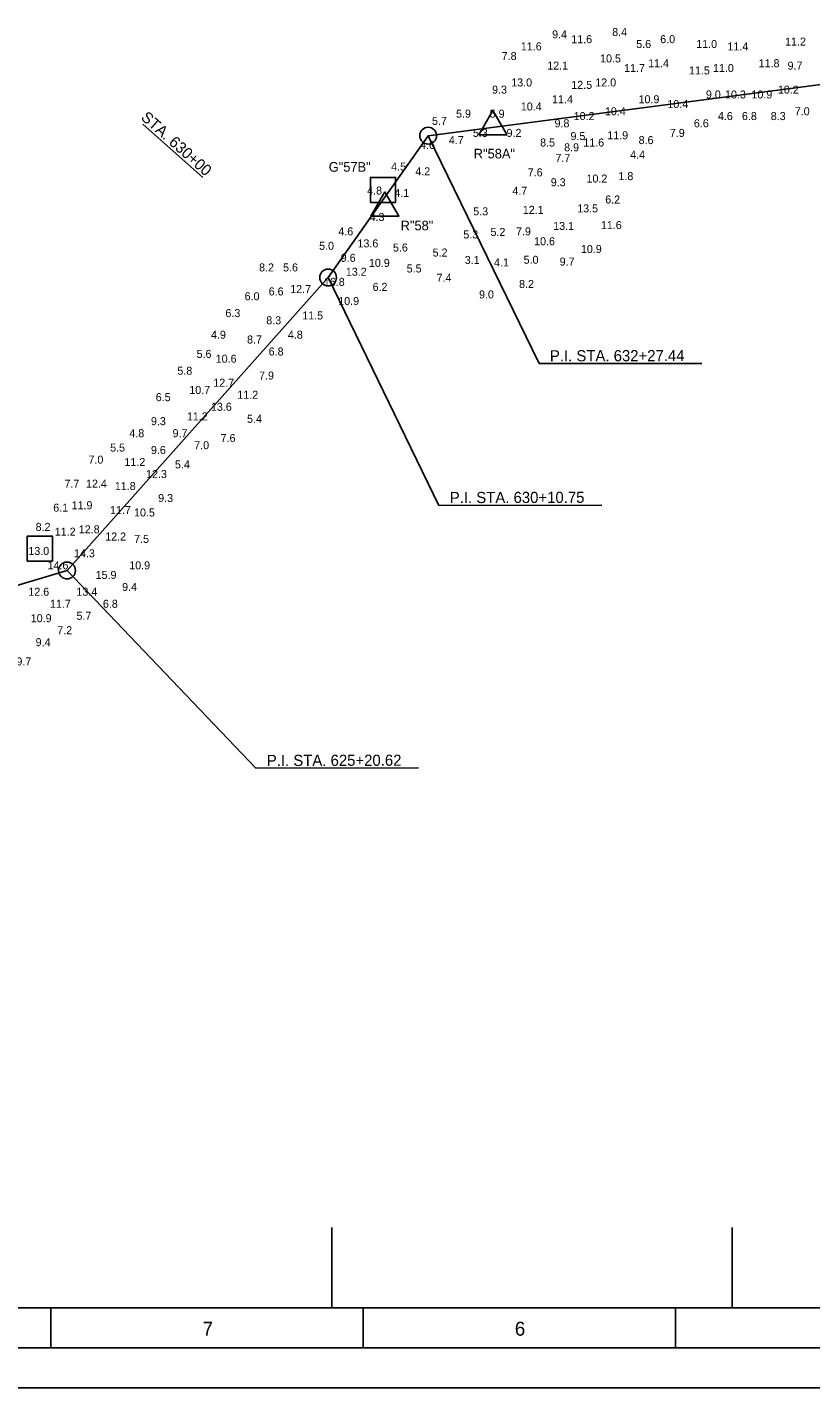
# Model space of a CAD drawing. Extents: x 442804 to 447204, y 1614037 to 1617437.
# Drawn here: x 444120 to 445098, y 1614037 to 1615736 of the extents above; entities that cross this region are included whole.
import ezdxf

# ---------------------------------------------------------------- set-up
doc = ezdxf.new("R2010")
doc.units = 0
for name, color, linetype in [('Default', 7, 'Continuous'), ('G-ANNO-NPLT', 7, 'Continuous'), ('G-ANNO-TTLB', 7, 'Continuous'), ('V-ALGN-TEXT', 7, 'Continuous'), ('V-CHAN-CNTR', 7, 'Continuous'), ('V-CHAN-CNTR-IDEN', 7, 'Continuous'), ('V-CHAN-NAID', 7, 'Continuous'), ('V-TOPO-COOR-STAT', 7, 'Continuous'), ('V-TOPO-SOUN', 7, 'Continuous')]:
    doc.layers.add(name, color=color, linetype=linetype)

msp = doc.modelspace()

# ---------------------------------------------------------------- linework, layer by layer
at = {"layer": 'G-ANNO-NPLT'}
msp.add_lwpolyline([(442804.3, 1617437.2), (447204.3, 1617437.2), (447204.3, 1614037.3), (442804.3, 1614037.3)], close=True, dxfattribs=at)
at = {"layer": 'G-ANNO-TTLB'}
for p, q in [((444149.3, 1614087.3), (444149.3, 1614137.3)), ((444539.3, 1614087.3), (444539.3, 1614137.3)), ((444929.3, 1614087.3), (444929.3, 1614137.3))]:
    msp.add_line(p, q, dxfattribs=at)
for points in [[(442854.3, 1614087.3), (447154.3, 1614087.3), (447154.3, 1617387.2), (442854.3, 1617387.2)], [(447104.3, 1617337.2), (442979.3, 1617337.2), (442979.3, 1614137.3), (447104.3, 1614137.3)]]:
    msp.add_lwpolyline(points, close=True, dxfattribs=at)
at = {"layer": 'V-ALGN-TEXT'}
for p, q in [((444264.2, 1615615.3), (444338.9, 1615548.8)), ((444620.4, 1615600.8), (444758.9, 1615316.2)), ((444495.4, 1615423.8), (444633.9, 1615139.2)), ((444758.9, 1615316.2), (444962.2, 1615316.5)), ((444633.9, 1615139.2), (444837.2, 1615139.5)), ((444169.4, 1615057.8), (444405.1, 1614810.9)), ((444405.1, 1614810.9), (444608.4, 1614811.3))]:
    msp.add_line(p, q, dxfattribs=at)
at = {"layer": 'V-CHAN-CNTR'}
for p, q in [((444620.4, 1615600.8), (445465.4, 1615710.8)), ((444495.4, 1615423.8), (444620.4, 1615600.8)), ((444169.4, 1615057.8), (444495.4, 1615423.8)), ((443592.4, 1614884.8), (444169.4, 1615057.8))]:
    msp.add_line(p, q, dxfattribs=at)
at = {"layer": 'V-CHAN-CNTR-IDEN'}
for centre in [(444620.4, 1615600.8), (444495.4, 1615423.8), (444169.4, 1615057.8)]:
    msp.add_circle(centre, 10.5, dxfattribs=at)
at = {"layer": 'V-CHAN-NAID'}
for p, q in [((444683.5, 1615601.9), (444701.1, 1615632.3)), ((444701.1, 1615632.3), (444718.5, 1615602.1)), ((444718.6, 1615601.9), (444683.5, 1615601.9)), ((444548.9, 1615500.2), (444566.4, 1615530.6)), ((444566.4, 1615530.6), (444583.9, 1615500.4)), ((444584, 1615500.2), (444548.9, 1615500.2))]:
    msp.add_line(p, q, dxfattribs=at)
for points in [[(444548.3, 1615517.4), (444548.3, 1615548.8), (444579.6, 1615548.8), (444579.6, 1615517.4)], [(444119.8, 1615069.6), (444119.8, 1615100.9), (444151.1, 1615100.9), (444151.1, 1615069.6)]]:
    msp.add_lwpolyline(points, close=True, dxfattribs=at)
at = {"layer": 'V-TOPO-COOR-STAT'}
for p, q in [((444500, 1614137.3), (444500, 1614237.3)), ((445000, 1614137.3), (445000, 1614237.3))]:
    msp.add_line(p, q, dxfattribs=at)

# ---------------------------------------------------------------- texts
at = {"layer": 'Default'}
for s, p in [('8.4', (444850.2, 1615725.3)), ('11.6 ', (444736.1, 1615707.3)), ('9.4', (444775.2, 1615722.3)), ('11.6 ', (444799.1, 1615716.3)), ('5.6', (444880.2, 1615710.3)), ('6.0', (444910.2, 1615716.3)), ('11.0 ', (444955.1, 1615710.3)), ('11.4 ', (444994.1, 1615707.3)), ('11.2 ', (445066.1, 1615713.3)), ('7.8', (444712.2, 1615695.3)), ('10.5 ', (444835.1, 1615692.3)), ('12.1 ', (444769.1, 1615683.3)), ('11.7 ', (444865.1, 1615680.3)), ('11.4 ', (444895.1, 1615686.3)), ('11.5 ', (444946.1, 1615677.3)), ('11.0 ', (444976.1, 1615680.3)), ('11.8 ', (445033.1, 1615686.3)), ('9.7', (445069.2, 1615683.3)), ('13.0 ', (444724.1, 1615662.3)), ('12.5 ', (444799.1, 1615659.3)), ('12.0 ', (444829.1, 1615662.3)), ('9.3', (444700.2, 1615653.3)), ('11.4 ', (444775.1, 1615641.3)), ('10.9 ', (444883.1, 1615641.3)), ('9.0', (444967.2, 1615647.3)), ('10.3 ', (444991.1, 1615647.3)), ('10.9 ', (445024.1, 1615647.3)), ('10.2 ', (445057.1, 1615653.3)), ('5.9', (444655.2, 1615623.3)), ('5.9', (444697.2, 1615623.3)), ('10.4 ', (444736.1, 1615632.3)), ('10.4 ', (444841.1, 1615626.3)), ('10.4 ', (444919.1, 1615635.3)), ('7.0', (445078.2, 1615626.3)), ('5.7', (444625.2, 1615614.3)), ('9.8', (444778.2, 1615611.3)), ('10.2 ', (444802.1, 1615620.3)), ('6.6', (444952.2, 1615611.3)), ('4.6', (444982.2, 1615620.3)), ('6.8', (445012.2, 1615620.3)), ('8.3', (445048.2, 1615620.3)), ('4.7', (444646.2, 1615590.3)), ('5.3', (444676.2, 1615599.3)), ('9.2', (444718.3, 1615599.3)), ('8.5', (444760.2, 1615587.3)), ('11.6 ', (444814.1, 1615587.3)), ('11.9 ', (444844.1, 1615596.3)), ('8.6', (444883.2, 1615590.3)), ('7.9', (444922.2, 1615599.3)), ('4.6', (444610.2, 1615584.3)), ('8.9', (444790.2, 1615581.3)), ('4.5', (444574.2, 1615557.3)), ('4.2', (444604.3, 1615551.3)), ('4.8', (444544.2, 1615527.3)), ('4.1', (444578.2, 1615524.3)), ('4.3', (444547.2, 1615494.3)), ('4.6', (444508.2, 1615476.3)), ('5.0', (444484.2, 1615458.3)), ('13.6 ', (444532.1, 1615461.3)), ('9.6', (444511.2, 1615443.3)), ('8.2', (444409.2, 1615431.3)), ('5.6', (444439.2, 1615431.3)), ('6.6', (444421.2, 1615401.3)), ('12.7 ', (444448.1, 1615404.3)), ('16.8 ', (444490.1, 1615413.3)), ('6.0', (444391.2, 1615395.3)), ('10.9 ', (444508.1, 1615389.3)), ('6.3', (444367.2, 1615374.3)), ('11.5 ', (444463.1, 1615371.3)), ('8.3', (444418.2, 1615365.3)), ('4.9', (444349.2, 1615347.3)), ('8.7', (444394.2, 1615341.3)), ('4.8', (444445.2, 1615347.3)), ('5.6', (444331.2, 1615323.3)), ('10.6 ', (444355.1, 1615317.3)), ('6.8', (444421.2, 1615326.3)), ('5.8', (444307.2, 1615302.3)), ('12.7 ', (444352.1, 1615287.3)), ('7.9', (444409.2, 1615296.3)), ('6.5', (444280.2, 1615269.3)), ('10.7 ', (444322.1, 1615278.3)), ('11.2 ', (444382.1, 1615272.3)), ('13.6 ', (444349.1, 1615257.3)), ('9.3', (444274.2, 1615239.3)), ('11.2 ', (444319.1, 1615245.3)), ('5.4', (444394.2, 1615242.3)), ('4.8', (444247.2, 1615224.3)), ('9.7', (444301.2, 1615224.3)), ('7.6', (444361.2, 1615218.3)), ('5.5', (444223.2, 1615206.3)), ('9.6', (444274.2, 1615203.3)), ('7.0', (444328.2, 1615209.3)), ('7.0', (444196.2, 1615191.3)), ('11.2 ', (444241.1, 1615188.3)), ('5.4', (444304.2, 1615185.3)), ('12.3 ', (444268.1, 1615173.3)), ('7.7', (444166.2, 1615161.3)), ('12.4 ', (444193.1, 1615161.3)), ('11.8 ', (444229.1, 1615158.3)), ('6.1', (444152.2, 1615131.3)), ('11.9 ', (444175.1, 1615134.3)), ('11.7 ', (444223.1, 1615128.3)), ('9.3', (444283.2, 1615143.3)), ('10.5 ', (444253.1, 1615125.3)), ('8.2', (444130.2, 1615107.3)), ('11.2 ', (444154.1, 1615101.3)), ('12.8 ', (444184.1, 1615104.3)), ('12.2 ', (444217.1, 1615095.3)), ('13.0 ', (444121.1, 1615077.3)), ('7.5', (444253.2, 1615092.3)), ('14.3 ', (444178.1, 1615074.3)), ('14.6 ', (444145.1, 1615059.3)), ('15.9 ', (444205.1, 1615047.3)), ('10.9 ', (444247.1, 1615059.3)), ('12.6 ', (444121.1, 1615026.3)), ('13.4 ', (444181.1, 1615026.3)), ('9.4', (444238.2, 1615032.3)), ('11.7 ', (444148.1, 1615011.3)), ('6.8', (444214.2, 1615011.3)), ('10.9 ', (444124.1, 1614993.3)), ('5.7', (444181.2, 1614996.3)), ('7.2', (444157.2, 1614978.3)), ('9.4', (444130.2, 1614963.3)), ('9.7', (444106.2, 1614939.3))]:
    msp.add_text(s, height=10, dxfattribs=at).set_placement(p)
at = {"layer": 'G-ANNO-TTLB'}
for s, p in [('7', (444338.7, 1614102.3)), ('6', (444728.6, 1614102.3))]:
    msp.add_text(s, height=17.5, dxfattribs=at).set_placement(p)
at = {"layer": 'V-ALGN-TEXT'}
for s, rotation, p in [('STA. 630+00', 318.309, (444260.8, 1615622.1)), ('P.I. STA. 632+27.44', 0.0976, (444772.4, 1615319)), ('P.I. STA. 630+10.75', 0.0976, (444647.4, 1615142)), ('P.I. STA. 625+20.62', 0.0976, (444418.9, 1614813.7))]:
    msp.add_text(s, height=13.92, rotation=rotation, dxfattribs=at).set_placement(p)
at = {"layer": 'V-CHAN-NAID'}
for s, p in [('R"58A"', (444677.3, 1615572.4)), ('G"57B"', (444496.2, 1615555.8)), ('R"58"', (444586, 1615482.6))]:
    msp.add_text(s, height=12, dxfattribs=at).set_placement(p)
at = {"layer": 'V-TOPO-SOUN'}
for s, p in [('9.5', (444798.1, 1615595.3)), ('4.4', (444872.7, 1615572.1)), ('7.7', (444779.3, 1615568)), ('7.6', (444744.7, 1615550)), ('9.3', (444773.5, 1615537.7)), ('10.2 ', (444818.1, 1615542.3)), ('1.8', (444858, 1615545.3)), ('4.7', (444725.5, 1615527)), ('12.1 ', (444738.6, 1615503.2)), ('13.5 ', (444806.5, 1615505)), ('6.2', (444841.5, 1615516.1)), ('5.3', (444676.7, 1615501.3)), ('5.3', (444664.3, 1615472.5)), ('5.2', (444698.2, 1615475.6)), ('7.9', (444730.1, 1615476.3)), ('13.1 ', (444776.5, 1615483.1)), ('11.6 ', (444836.1, 1615484.2)), ('5.6', (444576.4, 1615456.1)), ('10.6 ', (444752.7, 1615464)), ('10.9 ', (444811.1, 1615454.3)), ('10.9 ', (444546.4, 1615437)), ('5.2', (444626, 1615449.9)), ('3.1', (444666.1, 1615440.6)), ('4.1', (444702.6, 1615437.5)), ('5.0', (444739.6, 1615440.9)), ('9.7', (444784.6, 1615438.6)), ('13.2 ', (444517.6, 1615425.9)), ('5.5', (444593.6, 1615430)), ('7.4', (444630.9, 1615418.4)), ('6.2', (444551, 1615407)), ('8.2', (444733.9, 1615410.6)), ('9.0', (444683.9, 1615397.6))]:
    msp.add_text(s, height=10, dxfattribs=at).set_placement(p)

doc.saveas('drawing.dxf')
